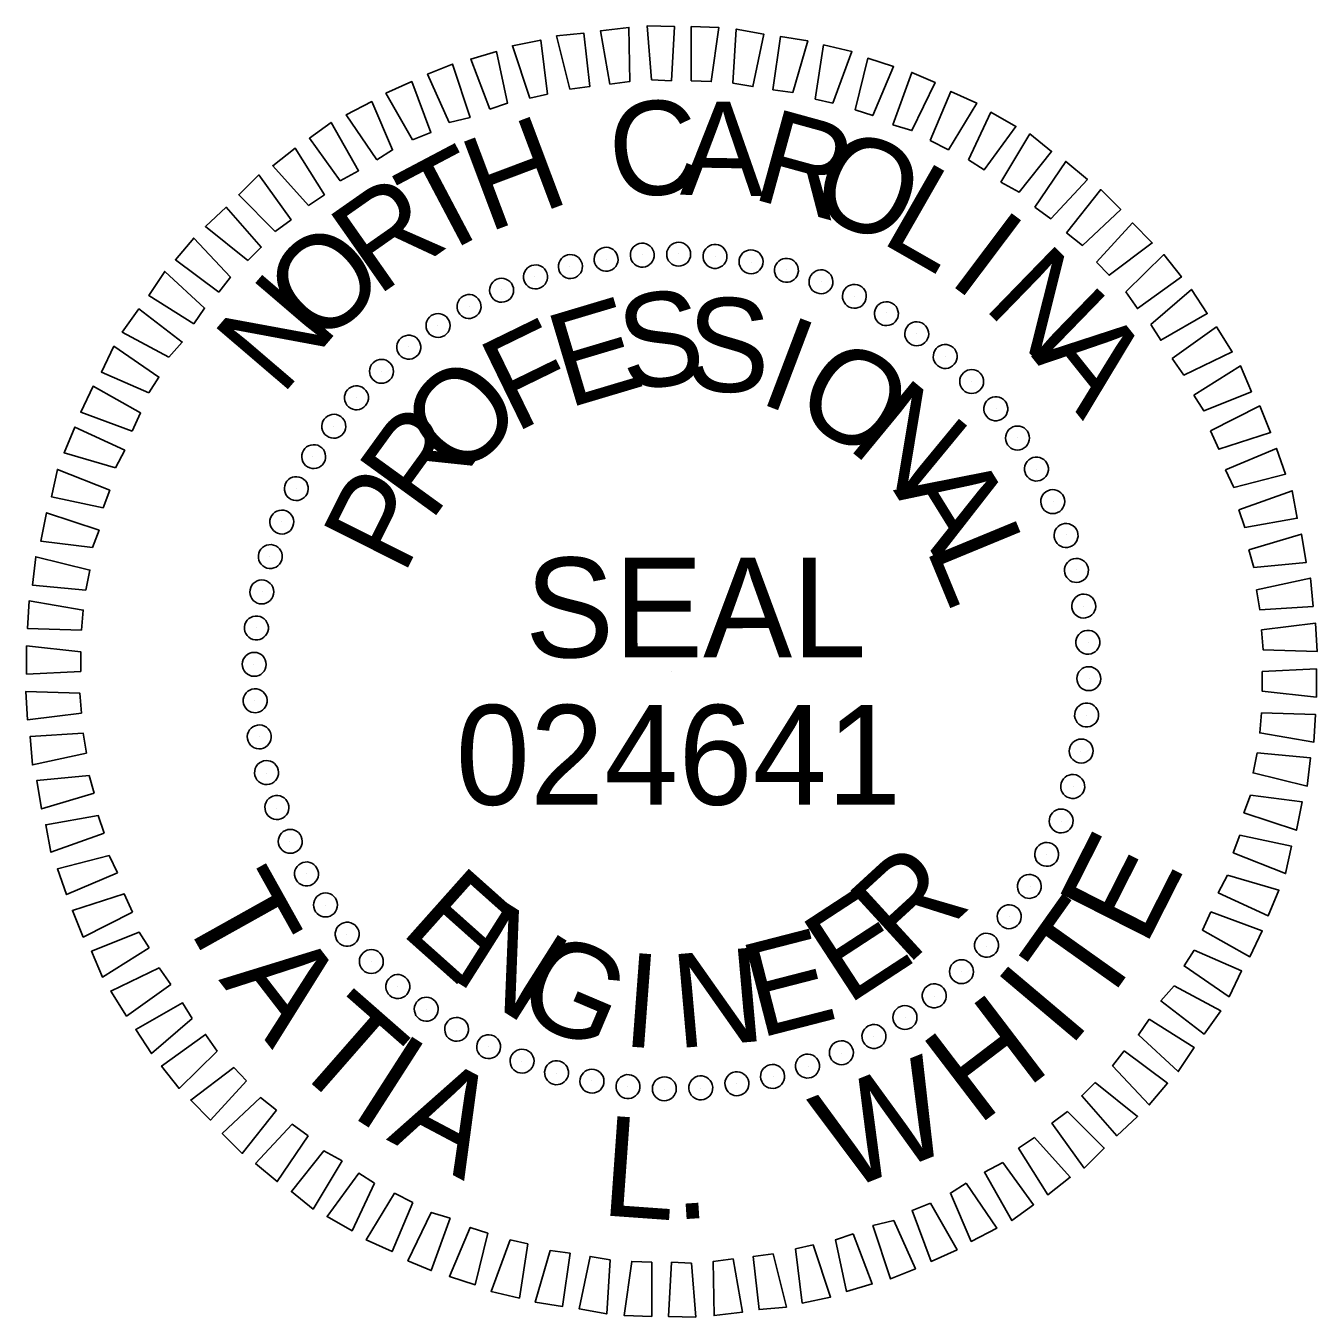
# Model space of a CAD drawing. Extents: x 2241081 to 2251104, y 658534 to 663427.
# Drawn here: x 2249518.9 to 2249596.5, y 662760.7 to 662838.3 of the extents above; entities that cross this region are included whole.
import ezdxf

# ---------------------------------------------------------------- set-up
doc = ezdxf.new("R2010")
doc.units = 0
doc.layers.add('Sheet Professional Seal CELL', color=7, linetype='Continuous')

msp = doc.modelspace()

# ---------------------------------------------------------------- linework, layer by layer
at = {"layer": 'Sheet Professional Seal CELL'}
for p, q in [((2249555.918, 662824.587), (2249555.918, 662824.587)), ((2249558.118, 662824.637), (2249558.118, 662824.637)), ((2249551.568, 662823.886), (2249551.568, 662823.886)), ((2249553.768, 662824.286), (2249553.768, 662824.286)), ((2249560.318, 662824.488), (2249560.318, 662824.488)), ((2249562.468, 662824.138), (2249562.468, 662824.138)), ((2249549.468, 662823.285), (2249549.468, 662823.285)), ((2249564.568, 662823.689), (2249564.568, 662823.689)), ((2249547.468, 662822.485), (2249547.468, 662822.485)), ((2249566.668, 662822.989), (2249566.668, 662822.989)), ((2249545.518, 662821.484), (2249545.518, 662821.484)), ((2249568.668, 662822.09), (2249568.668, 662822.09)), ((2249570.618, 662821.09), (2249570.618, 662821.09)), ((2249543.619, 662820.334), (2249543.619, 662820.334)), ((2249572.419, 662819.841), (2249572.419, 662819.841)), ((2249541.869, 662819.083), (2249541.869, 662819.083)), ((2249574.169, 662818.491), (2249574.169, 662818.491)), ((2249540.219, 662817.583), (2249540.219, 662817.583)), ((2249575.72, 662816.992), (2249575.72, 662816.992)), ((2249538.72, 662816.032), (2249538.72, 662816.032)), ((2249577.22, 662815.342), (2249577.22, 662815.342)), ((2249537.37, 662814.282), (2249537.37, 662814.282)), ((2249578.47, 662813.592), (2249578.47, 662813.592)), ((2249536.121, 662812.482), (2249536.121, 662812.482)), ((2249579.621, 662811.693), (2249579.621, 662811.693)), ((2249535.121, 662810.532), (2249535.121, 662810.532)), ((2249580.621, 662809.743), (2249580.621, 662809.743)), ((2249534.222, 662808.531), (2249534.222, 662808.531)), ((2249581.422, 662807.743), (2249581.422, 662807.743)), ((2249533.522, 662806.431), (2249533.522, 662806.431)), ((2249582.022, 662805.643), (2249582.022, 662805.643)), ((2249533.073, 662804.331), (2249533.073, 662804.331)), ((2249582.423, 662803.443), (2249582.423, 662803.443)), ((2249532.723, 662802.181), (2249532.723, 662802.181)), ((2249582.723, 662801.293), (2249582.723, 662801.293)), ((2249532.574, 662799.981), (2249532.574, 662799.981)), ((2249557.674, 662799.537), (2249557.674, 662799.537)), ((2249582.774, 662799.093), (2249582.774, 662799.093)), ((2249532.624, 662797.781), (2249532.624, 662797.781)), ((2249582.625, 662796.893), (2249582.625, 662796.893)), ((2249532.925, 662795.631), (2249532.925, 662795.631)), ((2249582.275, 662794.743), (2249582.275, 662794.743)), ((2249533.325, 662793.431), (2249533.325, 662793.431)), ((2249581.826, 662792.643), (2249581.826, 662792.643)), ((2249533.926, 662791.331), (2249533.926, 662791.331)), ((2249581.126, 662790.543), (2249581.126, 662790.543)), ((2249534.726, 662789.331), (2249534.726, 662789.331)), ((2249580.227, 662788.543), (2249580.227, 662788.543)), ((2249535.727, 662787.382), (2249535.727, 662787.382)), ((2249579.227, 662786.593), (2249579.227, 662786.593)), ((2249536.877, 662785.482), (2249536.877, 662785.482)), ((2249577.978, 662784.792), (2249577.978, 662784.792)), ((2249538.128, 662783.732), (2249538.128, 662783.732)), ((2249576.628, 662783.042), (2249576.628, 662783.042)), ((2249539.628, 662782.083), (2249539.628, 662782.083)), ((2249575.128, 662781.492), (2249575.128, 662781.492)), ((2249541.179, 662780.583), (2249541.179, 662780.583)), ((2249573.479, 662779.991), (2249573.479, 662779.991)), ((2249542.929, 662779.234), (2249542.929, 662779.234)), ((2249571.729, 662778.741), (2249571.729, 662778.741)), ((2249544.729, 662777.984), (2249544.729, 662777.984)), ((2249569.829, 662777.59), (2249569.829, 662777.59)), ((2249546.679, 662776.984), (2249546.679, 662776.984)), ((2249567.88, 662776.59), (2249567.88, 662776.59)), ((2249548.68, 662776.085), (2249548.68, 662776.085)), ((2249565.88, 662775.789), (2249565.88, 662775.789)), ((2249550.78, 662775.385), (2249550.78, 662775.385)), ((2249552.88, 662774.936), (2249552.88, 662774.936)), ((2249563.78, 662775.189), (2249563.78, 662775.189)), ((2249555.03, 662774.587), (2249555.03, 662774.587)), ((2249557.23, 662774.437), (2249557.23, 662774.437)), ((2249559.43, 662774.488), (2249559.43, 662774.488)), ((2249561.58, 662774.788), (2249561.58, 662774.788))]:
    msp.add_line(p, q, dxfattribs=at)
for points in [[(2249551.565, 662834.536), (2249550.764, 662837.735), (2249552.414, 662837.886), (2249552.765, 662834.686)], [(2249553.965, 662834.836), (2249553.414, 662838.036), (2249555.114, 662838.237), (2249555.165, 662834.987)], [(2249556.465, 662835.087), (2249556.214, 662838.337), (2249557.864, 662838.287), (2249557.665, 662835.037)], [(2249558.865, 662835.037), (2249558.864, 662838.287), (2249560.514, 662838.238), (2249560.065, 662834.988)], [(2249561.365, 662834.888), (2249561.564, 662838.138), (2249563.214, 662837.839), (2249562.565, 662834.688)], [(2249549.165, 662833.985), (2249548.114, 662837.135), (2249549.814, 662837.485), (2249550.215, 662834.235)], [(2249563.765, 662834.489), (2249564.214, 662837.689), (2249565.864, 662837.439), (2249564.965, 662834.339)], [(2249566.315, 662833.939), (2249566.814, 662837.189), (2249568.515, 662836.79), (2249567.365, 662833.69)], [(2249546.765, 662833.334), (2249545.615, 662836.334), (2249547.165, 662836.785), (2249547.815, 662833.685)], [(2249568.715, 662833.29), (2249569.465, 662836.39), (2249571.015, 662835.891), (2249569.766, 662832.94)], [(2249544.316, 662832.534), (2249543.015, 662835.434), (2249544.515, 662836.034), (2249545.566, 662832.834)], [(2249570.966, 662832.391), (2249572.115, 662835.541), (2249573.515, 662834.941), (2249572.116, 662832.041)], [(2249542.116, 662831.483), (2249540.515, 662834.283), (2249542.065, 662834.983), (2249543.216, 662831.934)], [(2249573.216, 662831.441), (2249574.465, 662834.391), (2249576.015, 662833.692), (2249574.316, 662830.891)], [(2249539.966, 662830.283), (2249538.116, 662832.982), (2249539.665, 662833.783), (2249540.916, 662830.883)], [(2249575.516, 662830.292), (2249576.865, 662833.142), (2249578.366, 662832.292), (2249576.466, 662829.692)], [(2249537.766, 662829.032), (2249535.916, 662831.582), (2249537.216, 662832.532), (2249538.866, 662829.633)], [(2249577.467, 662828.942), (2249579.216, 662831.843), (2249580.516, 662830.793), (2249578.567, 662828.342)], [(2249535.867, 662827.532), (2249533.716, 662829.931), (2249535.066, 662830.982), (2249536.817, 662828.182)], [(2249579.517, 662827.443), (2249581.366, 662830.193), (2249582.666, 662829.093), (2249580.467, 662826.743)], [(2249533.867, 662825.981), (2249531.667, 662828.181), (2249532.866, 662829.381), (2249534.817, 662826.681)], [(2249581.417, 662825.893), (2249583.467, 662828.494), (2249584.667, 662827.294), (2249582.367, 662825.143)], [(2249532.218, 662824.231), (2249529.667, 662826.28), (2249530.917, 662827.431), (2249533.017, 662825.031)], [(2249583.218, 662824.144), (2249585.367, 662826.494), (2249586.567, 662825.294), (2249583.968, 662823.344)], [(2249530.468, 662822.33), (2249527.868, 662824.28), (2249528.967, 662825.58), (2249531.168, 662823.231)], [(2249584.968, 662822.344), (2249587.268, 662824.595), (2249588.318, 662823.245), (2249585.668, 662821.344)], [(2249528.969, 662820.43), (2249526.268, 662822.129), (2249527.218, 662823.58), (2249529.618, 662821.38)], [(2249586.469, 662820.394), (2249588.918, 662822.495), (2249589.868, 662821.045), (2249587.069, 662819.445)], [(2249527.469, 662818.43), (2249524.669, 662819.929), (2249525.668, 662821.329), (2249528.269, 662819.33)], [(2249587.769, 662818.345), (2249590.419, 662820.245), (2249591.369, 662818.746), (2249588.469, 662817.345)], [(2249526.27, 662816.279), (2249523.419, 662817.529), (2249524.169, 662819.079), (2249526.869, 662817.23)], [(2249589.07, 662816.145), (2249591.869, 662817.896), (2249592.52, 662816.346), (2249589.67, 662815.195)], [(2249525.27, 662813.979), (2249522.17, 662815.128), (2249522.92, 662816.679), (2249525.77, 662815.079)], [(2249590.07, 662813.995), (2249593.02, 662815.496), (2249593.67, 662813.896), (2249590.571, 662812.895)], [(2249524.271, 662811.779), (2249521.171, 662812.678), (2249521.82, 662814.228), (2249524.821, 662812.829)], [(2249590.971, 662811.646), (2249594.021, 662812.946), (2249594.571, 662811.396), (2249591.471, 662810.596)], [(2249523.521, 662809.379), (2249520.421, 662810.028), (2249520.771, 662811.678), (2249523.921, 662810.429)], [(2249591.771, 662809.246), (2249594.971, 662810.397), (2249595.272, 662808.747), (2249592.122, 662808.196)], [(2249522.872, 662806.979), (2249519.772, 662807.378), (2249520.121, 662809.078), (2249523.272, 662808.029)], [(2249592.372, 662806.846), (2249595.522, 662807.797), (2249595.822, 662806.097), (2249592.672, 662805.796)], [(2249522.473, 662804.428), (2249519.273, 662804.728), (2249519.472, 662806.428), (2249522.722, 662805.628)], [(2249592.823, 662804.446), (2249596.072, 662805.147), (2249596.223, 662803.447), (2249593.023, 662803.246)], [(2249522.223, 662802.028), (2249518.973, 662802.128), (2249519.073, 662803.778), (2249522.323, 662803.228)], [(2249593.123, 662802.046), (2249596.373, 662802.447), (2249596.474, 662800.747), (2249593.224, 662800.846)], [(2249522.174, 662799.528), (2249518.924, 662799.378), (2249518.923, 662801.078), (2249522.174, 662800.728)], [(2249593.174, 662799.546), (2249596.424, 662799.697), (2249596.424, 662797.997), (2249593.174, 662798.346)], [(2249522.224, 662797.028), (2249518.975, 662796.628), (2249518.874, 662798.328), (2249522.124, 662798.228)], [(2249593.124, 662797.046), (2249596.375, 662796.947), (2249596.275, 662795.297), (2249593.025, 662795.846)], [(2249522.525, 662794.628), (2249519.275, 662793.928), (2249519.125, 662795.628), (2249522.325, 662795.828)], [(2249592.875, 662794.646), (2249596.075, 662794.347), (2249595.876, 662792.647), (2249592.625, 662793.446)], [(2249522.976, 662792.229), (2249519.826, 662791.278), (2249519.526, 662792.978), (2249522.675, 662793.278)], [(2249592.476, 662792.096), (2249595.576, 662791.697), (2249595.226, 662789.997), (2249592.076, 662791.046)], [(2249523.576, 662789.829), (2249520.377, 662788.678), (2249520.076, 662790.328), (2249523.226, 662790.879)], [(2249591.826, 662789.696), (2249594.926, 662789.047), (2249594.577, 662787.396), (2249591.427, 662788.646)], [(2249524.377, 662787.429), (2249521.327, 662786.128), (2249520.777, 662787.678), (2249523.877, 662788.479)], [(2249591.077, 662787.296), (2249594.177, 662786.396), (2249593.528, 662784.846), (2249590.527, 662786.245)], [(2249525.277, 662785.079), (2249522.328, 662783.578), (2249521.677, 662785.178), (2249524.777, 662786.179)], [(2249590.077, 662785.095), (2249593.178, 662783.946), (2249592.428, 662782.396), (2249589.578, 662783.995)], [(2249526.278, 662782.929), (2249523.478, 662781.179), (2249522.828, 662782.728), (2249525.678, 662783.879)], [(2249589.078, 662782.795), (2249591.928, 662781.546), (2249591.179, 662779.996), (2249588.478, 662781.845)], [(2249527.579, 662780.73), (2249524.929, 662778.829), (2249523.979, 662780.329), (2249526.878, 662781.73)], [(2249587.879, 662780.645), (2249590.679, 662779.145), (2249589.679, 662777.745), (2249587.079, 662779.745)], [(2249528.879, 662778.68), (2249526.43, 662776.579), (2249525.479, 662778.029), (2249528.279, 662779.63)], [(2249586.379, 662778.644), (2249589.08, 662776.945), (2249588.13, 662775.495), (2249585.729, 662777.694)], [(2249530.38, 662776.73), (2249528.08, 662774.48), (2249527.03, 662775.83), (2249529.679, 662777.73)], [(2249584.88, 662776.744), (2249587.48, 662774.795), (2249586.38, 662773.494), (2249584.18, 662775.844)], [(2249532.13, 662774.931), (2249529.981, 662772.58), (2249528.78, 662773.78), (2249531.38, 662775.731)], [(2249583.13, 662774.844), (2249585.681, 662772.794), (2249584.431, 662771.644), (2249582.33, 662774.043)], [(2249533.93, 662773.181), (2249531.881, 662770.581), (2249530.681, 662771.78), (2249532.98, 662773.931)], [(2249581.48, 662773.093), (2249583.681, 662770.894), (2249582.481, 662769.693), (2249580.531, 662772.393)], [(2249535.831, 662771.632), (2249533.982, 662768.881), (2249532.681, 662769.981), (2249534.881, 662772.332)], [(2249579.481, 662771.543), (2249581.631, 662769.143), (2249580.282, 662768.093), (2249578.531, 662770.892)], [(2249537.881, 662770.132), (2249536.132, 662767.232), (2249534.832, 662768.281), (2249536.781, 662770.732)], [(2249577.581, 662770.042), (2249579.432, 662767.493), (2249578.132, 662766.542), (2249576.481, 662769.442)], [(2249539.832, 662768.783), (2249538.482, 662765.932), (2249536.982, 662766.782), (2249538.881, 662769.383)], [(2249575.382, 662768.792), (2249577.232, 662766.092), (2249575.682, 662765.292), (2249574.432, 662768.191)], [(2249542.132, 662767.633), (2249540.883, 662764.683), (2249539.332, 662765.383), (2249541.032, 662768.183)], [(2249573.232, 662767.591), (2249574.833, 662764.791), (2249573.283, 662764.091), (2249572.132, 662767.141)], [(2249544.382, 662766.684), (2249543.233, 662763.534), (2249541.833, 662764.133), (2249543.232, 662767.034)], [(2249571.032, 662766.541), (2249572.333, 662763.641), (2249570.833, 662763.04), (2249569.782, 662766.24)], [(2249546.632, 662765.784), (2249545.883, 662762.684), (2249544.333, 662763.184), (2249545.582, 662766.134)], [(2249568.582, 662765.74), (2249569.733, 662762.74), (2249568.183, 662762.29), (2249567.532, 662765.39)], [(2249549.032, 662765.135), (2249548.533, 662761.885), (2249546.833, 662762.284), (2249547.982, 662765.385)], [(2249566.182, 662765.089), (2249567.233, 662761.94), (2249565.533, 662761.589), (2249565.133, 662764.839)], [(2249551.583, 662764.586), (2249551.133, 662761.386), (2249549.483, 662761.635), (2249550.383, 662764.735)], [(2249553.983, 662764.186), (2249553.784, 662760.936), (2249552.133, 662761.236), (2249552.783, 662764.386)], [(2249556.483, 662764.037), (2249556.484, 662760.787), (2249554.834, 662760.836), (2249555.283, 662764.087)], [(2249561.383, 662764.238), (2249561.933, 662761.038), (2249560.234, 662760.838), (2249560.183, 662764.088)], [(2249563.783, 662764.539), (2249564.583, 662761.339), (2249562.933, 662761.189), (2249562.583, 662764.388)], [(2249558.883, 662763.988), (2249559.134, 662760.738), (2249557.484, 662760.787), (2249557.683, 662764.037)]]:
    msp.add_lwpolyline(points, close=True, dxfattribs=at)
for centre, major_axis in [((2249551.6, 662823.871), (-0.174, 0.699)), ((2249553.744, 662824.307), (-0.113, 0.711)), ((2249555.918, 662824.556), (-0.05, 0.718)), ((2249558.105, 662824.613), (0.012, 0.72)), ((2249560.289, 662824.48), (0.075, 0.716)), ((2249562.453, 662824.158), (0.137, 0.707)), ((2249549.503, 662823.249), (-0.235, 0.681)), ((2249564.581, 662823.647), (0.198, 0.692)), ((2249547.467, 662822.446), (-0.293, 0.658)), ((2249566.656, 662822.954), (0.258, 0.672)), ((2249545.509, 662821.47), (-0.349, 0.63)), ((2249568.663, 662822.082), (0.315, 0.647)), ((2249570.586, 662821.038), (0.371, 0.617)), ((2249543.644, 662820.326), (-0.403, 0.597)), ((2249572.41, 662819.831), (0.423, 0.583)), ((2249541.886, 662819.024), (-0.453, 0.559)), ((2249574.123, 662818.469), (0.472, 0.544)), ((2249540.247, 662817.574), (-0.5, 0.518)), ((2249575.711, 662816.964), (0.518, 0.5)), ((2249538.742, 662815.986), (-0.544, 0.472)), ((2249577.161, 662815.325), (0.559, 0.453)), ((2249537.38, 662814.274), (-0.583, 0.423)), ((2249578.463, 662813.567), (0.597, 0.403)), ((2249536.173, 662812.449), (-0.617, 0.371)), ((2249579.606, 662811.702), (0.63, 0.349)), ((2249535.129, 662810.526), (-0.647, 0.315)), ((2249580.583, 662809.744), (0.658, 0.293)), ((2249534.257, 662808.519), (-0.672, 0.258)), ((2249581.385, 662807.708), (0.681, 0.235)), ((2249533.564, 662806.444), (-0.692, 0.198)), ((2249582.007, 662805.611), (0.699, 0.174)), ((2249533.053, 662804.317), (-0.707, 0.137)), ((2249582.444, 662803.467), (0.711, 0.113)), ((2249532.731, 662802.153), (-0.716, 0.075)), ((2249582.692, 662801.293), (0.718, 0.05)), ((2249532.598, 662799.969), (-0.72, 0.012)), ((2249582.75, 662799.106), (0.72, -0.012)), ((2249532.655, 662797.781), (-0.718, -0.05)), ((2249582.617, 662796.922), (0.716, -0.075)), ((2249532.904, 662795.608), (-0.711, -0.113)), ((2249582.294, 662794.758), (0.707, -0.137)), ((2249533.34, 662793.464), (-0.699, -0.174)), ((2249581.784, 662792.63), (0.692, -0.198)), ((2249533.962, 662791.366), (-0.681, -0.235)), ((2249581.09, 662790.555), (0.672, -0.258)), ((2249534.765, 662789.331), (-0.658, -0.293)), ((2249580.218, 662788.548), (0.647, -0.315)), ((2249535.741, 662787.373), (-0.63, -0.349)), ((2249579.175, 662786.625), (0.617, -0.371)), ((2249536.885, 662785.507), (-0.597, -0.403)), ((2249577.968, 662784.801), (0.583, -0.423)), ((2249538.187, 662783.749), (-0.559, -0.453)), ((2249576.606, 662783.088), (0.544, -0.472)), ((2249539.637, 662782.111), (-0.518, -0.5)), ((2249575.1, 662781.501), (0.5, -0.518)), ((2249541.225, 662780.605), (-0.472, -0.544)), ((2249573.462, 662780.05), (0.453, -0.559)), ((2249542.937, 662779.243), (-0.423, -0.583)), ((2249571.704, 662778.748), (0.403, -0.597)), ((2249544.762, 662778.036), (-0.371, -0.617)), ((2249569.838, 662777.605), (0.349, -0.63)), ((2249546.685, 662776.993), (-0.315, -0.647)), ((2249567.881, 662776.628), (0.293, -0.658)), ((2249548.692, 662776.121), (-0.258, -0.672)), ((2249565.845, 662775.826), (0.235, -0.681)), ((2249550.767, 662775.427), (-0.198, -0.692)), ((2249552.895, 662774.917), (-0.137, -0.707)), ((2249563.747, 662775.204), (0.174, -0.699)), ((2249555.059, 662774.594), (-0.075, -0.716)), ((2249557.242, 662774.461), (-0.012, -0.72)), ((2249559.43, 662774.519), (0.05, -0.718)), ((2249561.603, 662774.767), (0.113, -0.711))]:
    msp.add_ellipse(centre, major_axis=major_axis, ratio=0.999708, dxfattribs=at)

# ---------------------------------------------------------------- texts
for s, height, rotation, p in [('C', 5.638, 6.23419, (2249554.217, 662827.886)), ('A', 5.638, 359.03464, (2249558.167, 662828.187)), ('R', 5.638, 344.63542, (2249562.367, 662827.988)), ('H', 5.638, 20.6338, (2249546.617, 662825.884)), ('O', 5.638, 337.43548, (2249565.717, 662827.239)), ('T', 5.638, 27.83409, (2249543.368, 662824.234)), ('L', 5.638, 330.23519, (2249570.117, 662825.39)), ('R', 5.639, 35.03482, (2249539.968, 662822.033)), ('I', 5.638, 323.03446, (2249574.168, 662822.991)), ('O', 5.638, 42.23606, (2249536.519, 662818.932)), ('N', 5.639, 315.83323, (2249576.318, 662821.442)), ('N', 5.639, 49.43782, (2249534.22, 662816.031)), ('S', 5.638, 7.26993, (2249554.87, 662816.387)), ('E', 5.638, 16.62539, (2249551.42, 662815.336)), ('S', 5.638, 357.91472, (2249558.47, 662816.437)), ('F', 5.638, 25.98135, (2249548.22, 662813.835)), ('I', 5.638, 339.20392, (2249562.77, 662815.738)), ('A', 5.639, 308.63147, (2249579.269, 662818.493)), ('O', 5.638, 329.8478, (2249564.77, 662815.039)), ('O', 5.639, 44.69556, (2249544.921, 662810.884)), ('N', 5.638, 320.49093, (2249568.12, 662813.04)), ('R', 5.639, 54.05397, (2249543.172, 662808.434)), ('P', 5.639, 63.41321, (2249541.572, 662805.233)), ('A', 5.639, 301.77459, (2249570.971, 662810.441)), ('L', 5.639, 292.41517, (2249572.922, 662806.991)), ('SEAL', 5.9982, 0.01432, (2249548.875, 662800.384)), ('024641', 5.9982, 0.01432, (2249544.705, 662791.526)), ('E', 5.998, 63.13321, (2249586.11, 662782.889)), ('R', 5.639, 42.49573, (2249571.778, 662781.791)), ('T', 5.998, 299.17946, (2249527.982, 662785.248)), ('E', 5.638, 318.29121, (2249541.278, 662783.883)), ('E', 5.638, 33.13841, (2249568.229, 662779.44)), ('T', 5.998, 54.61139, (2249583.329, 662778.859)), ('N', 5.638, 327.64827, (2249544.278, 662781.184)), ('G', 5.638, 337.00456, (2249548.079, 662778.935)), ('E', 5.638, 14.42608, (2249562.929, 662777.489)), ('A', 5.998, 307.70128, (2249530.428, 662781.006)), ('N', 5.638, 5.07071, (2249557.98, 662776.887)), ('I', 5.638, 355.71552, (2249554.629, 662777.036)), ('I', 5.998, 49.84692, (2249581.523, 662776.8)), ('T', 5.998, 318.77965, (2249534.496, 662776.115)), ('H', 5.998, 37.33533, (2249576.031, 662772.173)), ('I', 5.998, 327.30147, (2249538.223, 662772.939)), ('W', 5.998, 21.62807, (2249567.938, 662768.225)), ('A', 5.998, 332.06594, (2249540.499, 662771.416)), ('L', 5.998, 355.92704, (2249553.343, 662766.872)), ('.', 5.998, 3.79035, (2249557.853, 662766.586))]:
    msp.add_text(s, height=height, rotation=rotation, dxfattribs=at).set_placement(p)

doc.saveas('drawing.dxf')
